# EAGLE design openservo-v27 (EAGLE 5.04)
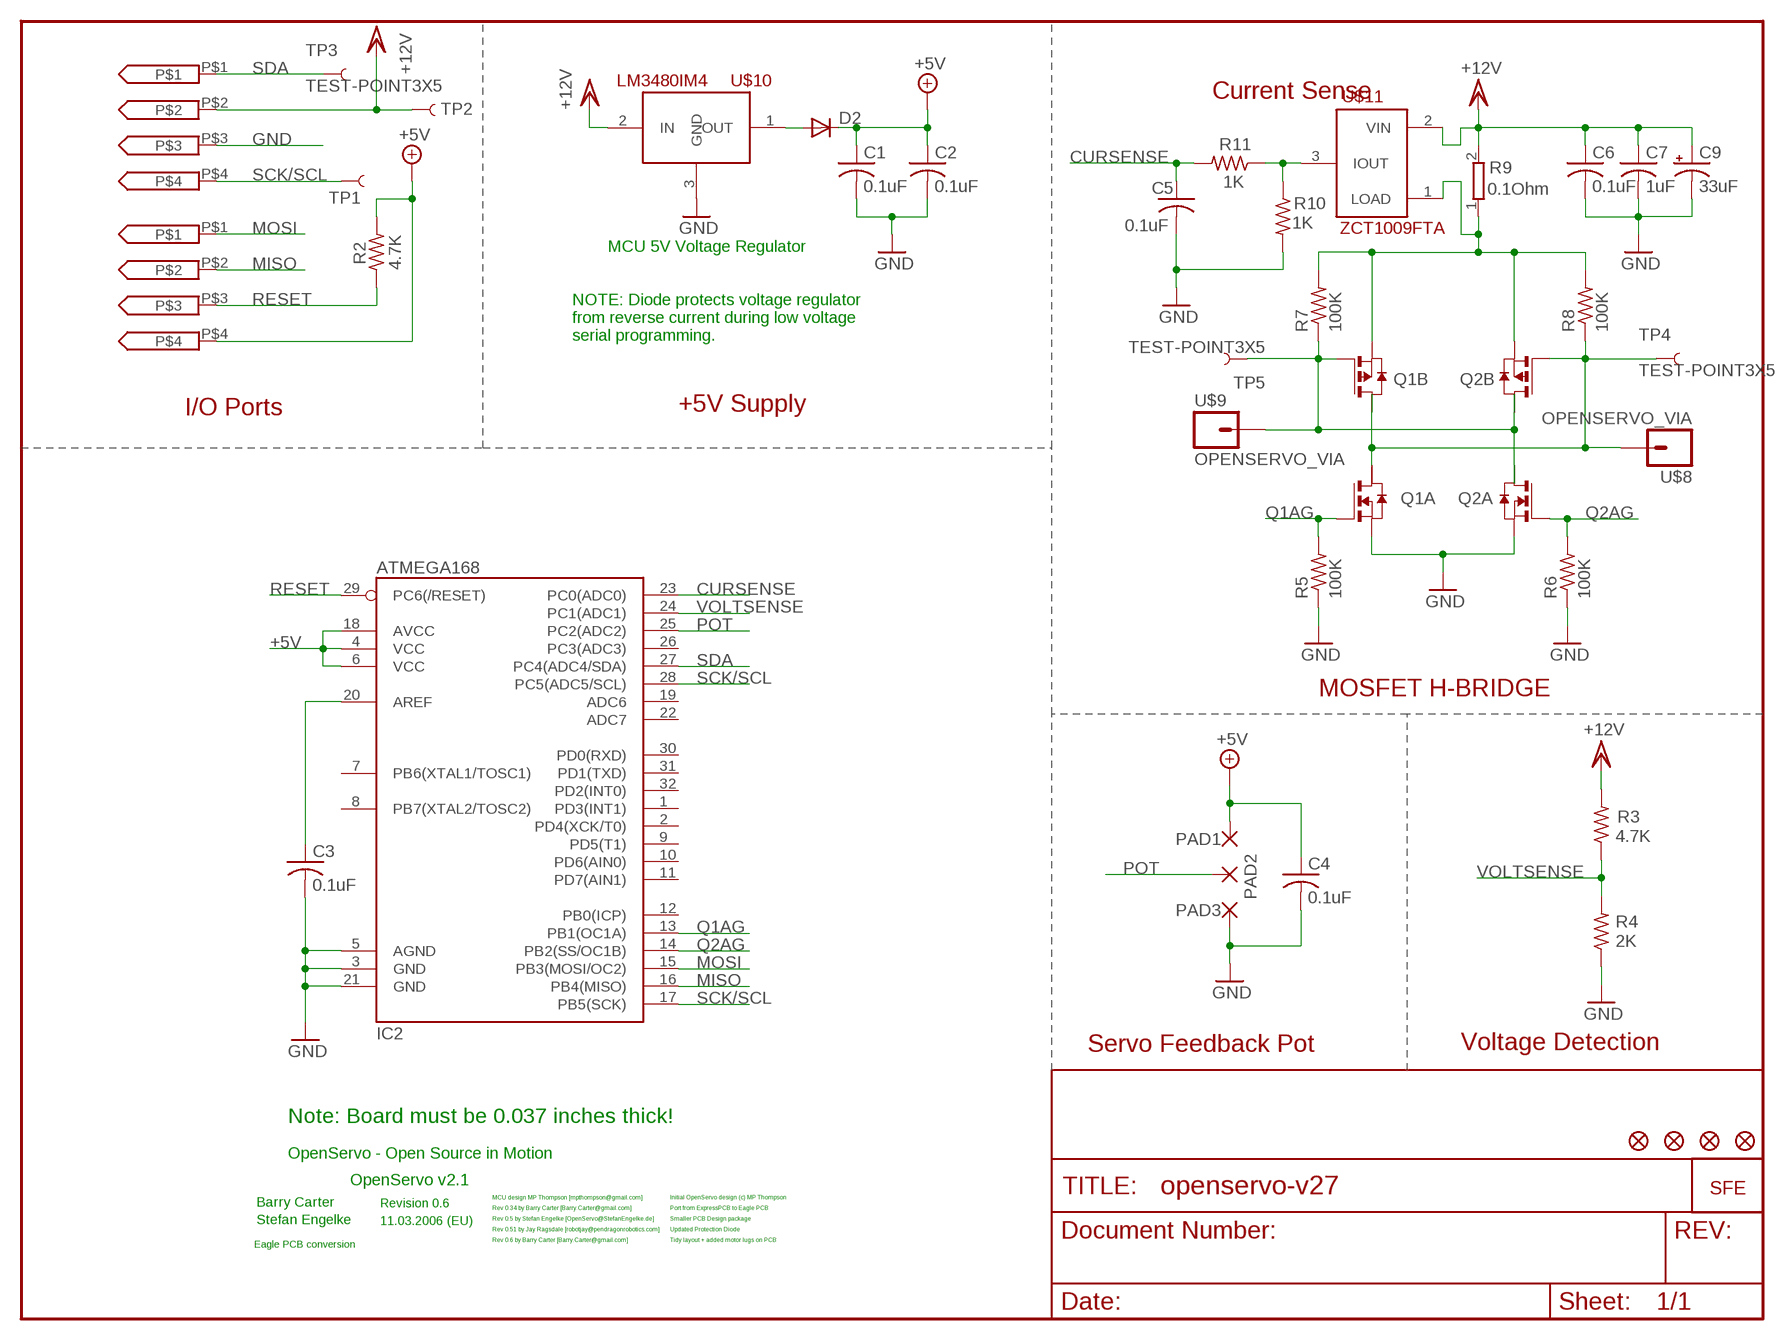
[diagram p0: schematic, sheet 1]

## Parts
C1  0.1uF  C-USC0402  [C0402]
C2  0.1uF  C-USC0402  [C0402]
C3  0.1uF  C-USC0402  [C0402]
C4  0.1uF  C-USC0402  [C0402]
C5  0.1uF  C-USC0402  [C0402]
C6  0.1uF  C-USC0402  [C0402]
C7  1uF  C-USC0402  [C0402]
C9  33uF  CAP_POL3528  [EIA3528]
D2  DIODESOD  [SOD-323]
IC2  ATMEGA168  [TQFP32-08]
PAD1  1,6/0,9  [1,6/0,9]
PAD2  1,6/0,9  [1,6/0,9]
PAD3  1,6/0,9  [1,6/0,9]
Q1  PN_MOSFET-SO8  [SO8]
Q2  PN_MOSFET-SO8  [SO8]
R2  4.7K  R-US_R0402  [R0402]
R3  4.7K  R-US_R0402  [R0402]
R4  2K  R-US_R0402  [R0402]
R5  100K  R-US_R0402  [R0402]
R6  100K  R-US_R0402  [R0402]
R7  100K  R-US_R0402  [R0402]
R8  100K  R-US_R0402  [R0402]
R9  0.1Ohm  R1206W  [R1206W]
R10  1K  R-US_R0402  [R0402]
R11  1K  R-US_R0402  [R0402]
TP1  TEST-POINT3X5  [PAD.03X.05]
TP2  TEST-POINT3X5  [PAD.03X.05]
TP3  TEST-POINT3X5  [PAD.03X.05]
TP4  TEST-POINT3X5  [PAD.03X.05]
TP5  TEST-POINT3X5  [PAD.03X.05]
U$1  4-EDGEVERSION2  4-EDGE  [4-PIN-EDGE]
U$2  4-EDGEVERSION2  4-EDGE  [4-PIN-EDGE]
U$3  FIDUCIAL1X2  [FIDUCIAL-1X2]
U$4  FIDUCIAL1X2  [FIDUCIAL-1X2]
U$5  FIDUCIAL1X2  [FIDUCIAL-1X2]
U$6  FIDUCIAL1X2  [FIDUCIAL-1X2]
U$7  LOGO-SFESK  [SFE-LOGO-FLAME]
U$8  OPENSERVO_VIA  [OPENSERVO_VIA]
U$9  OPENSERVO_VIA  [OPENSERVO_VIA]
U$10  LM3480IM4  [SOT23-3]
U$11  ZCT1009FTA  [SOT23-3]

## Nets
+5V: C1.1 C2.1 C4.1 D2.1(C) IC2.4(VCC) IC2.6(VCC) IC2.18(AVCC) PAD1.1(P) R2.2 U$2.P$4
CURSENSE: C5.1 IC2.23(PC0(ADC0)) R11.2
GND: C1.2 C2.2 C3.2 C4.2 C5.2 C6.2 C7.2 C9.C(-) IC2.3(GND) IC2.5(AGND) IC2.21(GND) PAD3.1(P) Q1.1(A:S) Q2.1(A:S) R4.1 R5.1 R6.1 R10.2 U$1.P$3 U$10.3(GND)
MISO: IC2.16(PB4(MISO)) U$2.P$2
MOSI: IC2.15(PB3(MOSI/OC2)) U$2.P$1
N$1: D2.2(A) U$10.1(OUT)
N$4: Q1.4(B:G) Q2.5(B:D) Q2.6(B:D2) Q2.7(A:D) Q2.8(A:D2) R7.1 TP5.P$1 U$9.P$1
N$5: Q1.5(B:D) Q1.6(B:D2) Q1.7(A:D) Q2.4(B:G) R8.1 TP4.P$1 U$8.P$1
N$10: Q1.3(B:S) Q2.3(B:S) R7.2 R8.2 R9.1 U$11.1(LOAD)
N$12: R10.1 R11.1 U$11.3(IOUT)
N$21: C3.1 IC2.20(AREF)
POT: IC2.25(PC2(ADC2)) PAD2.1(P)
Q1AG: IC2.13(PB1(OC1A)) Q1.2(A:G) R5.2
Q2AG: IC2.14(PB2(SS/OC1B)) Q2.2(A:G) R6.2
RESET: IC2.29(PC6(/RESET)) R2.1 U$2.P$3
SCK/SCL: IC2.17(PB5(SCK)) IC2.28(PC5(ADC5/SCL)) TP1.P$1 U$1.P$4
SDA: IC2.27(PC4(ADC4/SDA)) TP3.P$1 U$1.P$1
VCC/2: C6.1 C7.1 C9.A(+) R3.2 R9.2 TP2.P$1 U$1.P$2 U$10.2(IN) U$11.2(VIN) ; supply symbol labelled +12V
VOLTSENSE: IC2.24(PC1(ADC1)) R3.1 R4.2
Unconnected: IC2.1(PD3(INT1)) IC2.2(PD4(XCK/T0)) IC2.7(PB6(XTAL1/TOSC1)) IC2.8(PB7(XTAL2/TOSC2)) IC2.9(PD5(T1)) IC2.10(PD6(AIN0)) IC2.11(PD7(AIN1)) IC2.12(PB0(ICP)) IC2.19(ADC6) IC2.22(ADC7) IC2.26(PC3(ADC3)) IC2.30(PD0(RXD)) IC2.31(PD1(TXD)) IC2.32(PD2(INT0)) Q1.8(A:D2)

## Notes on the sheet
- Current Sense
- MCU 5V Voltage Regulator
- NOTE: Diode protects voltage regulator
- from reverse current during low voltage
- serial programming.
- I/O Ports | +5V Supply
- MOSFET H-BRIDGE
- Servo Feedback Pot | Voltage Detection
- Note: Board must be 0.037 inches thick!
- OpenServo - Open Source in Motion
- OpenServo v2.1
- MCU design MP Thompson [mpthompson@gmail.com] | Initial OpenServo design (c) MP Thompson
- Barry Carter | Revision 0.6
- Rev 0.34 by Barry Carter [Barry.Carter@gmail.com] | Port from ExpressPCB to Eagle PCB
- Rev 0.5 by Stefan Engelke [OpenServo@StefanEngelke.de] | Smaller PCB Design package
- Stefan Engelke | 11.03.2006 (EU)
- Rev 0.51 by Jay Ragsdale [robotjay@pendragonrobotics.com] | Updated Protection Diode
- Rev 0.6 by Barry Carter [Barry.Carter@gmail.com] | Tidy layout + added motor lugs on PCB
- Eagle PCB conversion

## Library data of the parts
C1-C7 = rcl:C-US: CAPACITOR, American symbol
C9 = SparkFun:CAP_POL: Capacitor Polarized
D2 = SparkFun:DIODE: Diode
IC2 = SparkFun:ATMEGA168
PAD1-PAD3 = wirepad:1,6/0,9: THROUGH-HOLE PAD
Q1 Q2 = zetex:PN_MOSFET-: DUAL N AND P-CHANNEL ENHANCEMENT MODE MOSFET source ZXMD63C02.pdf from http://www.zetex.com/
R2-R8 R10 R11 = rcl:R-US_: RESISTOR, American symbol
R9 = openservo:R1206W
TP1-TP5 = SparkFun:TEST-POINT
U$1 U$2 = openservo:4-EDGE
U$3-U$6 = SparkFun:FIDUCIAL: Fiducial Alignment Points
U$7 = SparkFun:LOGO-SFE: Spark Fun Electronics PCB Logo
U$8 U$9 = SparkFun:OPENSERVO_VIA
U$10 = SparkFun:LM3480IM4
U$11 = SparkFun:ZCT1009FTA

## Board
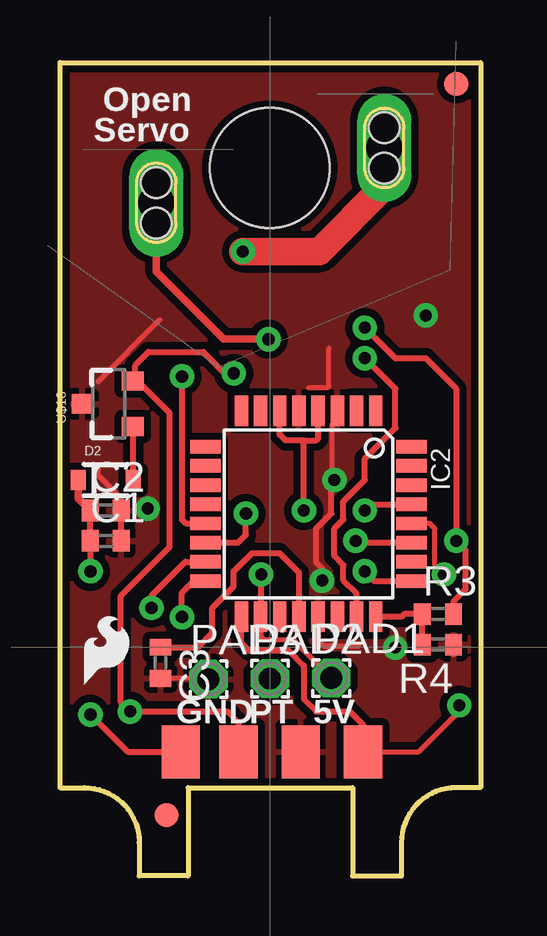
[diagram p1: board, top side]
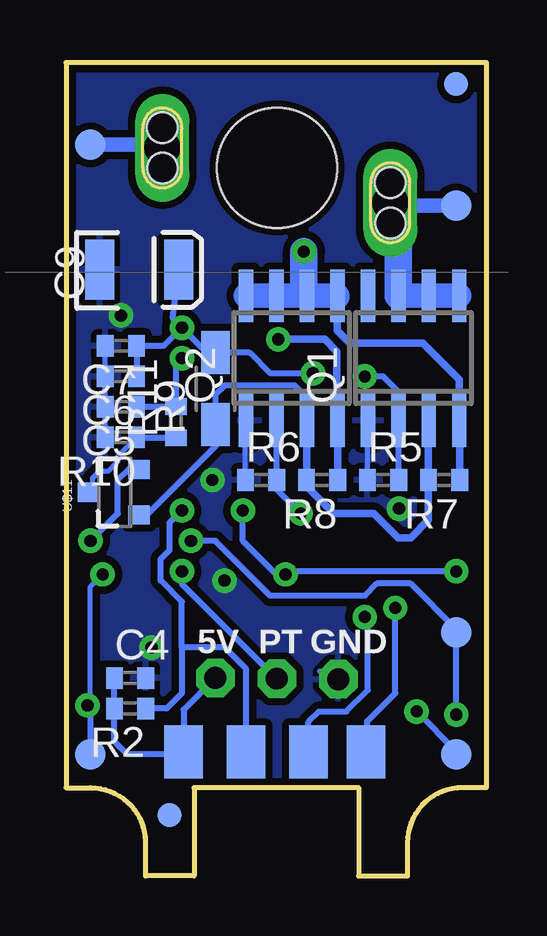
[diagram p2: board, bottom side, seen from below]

Size 17.53 x 33.91 mm. Coordinates in mm from the lower left corner, seen from the top.
Outline: 0,3.68 0,33.91 17.53,33.91 17.53,3.68 16.51,3.68 arc90 14.22,1.4 14.22,0 12.19,0 12.19,3.68 5.33,3.68 5.33,0 3.3,0 3.3,1.4 arc90 1.02,3.68 0,3.68
Copper layers (1*16): Top 0.035mm / dielectric 1.5mm / Bottom 0.035mm
Design rules "SparkFun": minimum track width 8mil, minimum drill 20mil, track to track 8mil, track to pad 8mil, pad to pad 8mil, via to via 8mil, smd to smd 8mil, copper to edge 10mil, drill to drill 8mil, minimum pad ring 12mil, minimum via ring 10mil, stop-mask expansion 4mil, vias tented up to drill 25mil, thermal gap 10mil
Holes 5 mm at 8.74,29.52
tKeepout: area 0.1,0 to 2.1,2; area 15.8,0 to 17.8,2; area 2.5,25.4 to 7.6,29.2; area 10.2,28.3 to 15.2,33
bKeepout: area 2.5,25.4 to 7.6,29.2; area 10.2,29.2 to 15.2,33

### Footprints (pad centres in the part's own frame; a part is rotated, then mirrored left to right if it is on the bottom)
C0402 = smd 0.7 x 0.9: 1 -0.65,0; 2 0.65,0
EIA3528 = smd 1.2 x 2.5: A 1.65,0; C -1.65,0
SOD-323 = smd 0.63 x 0.83: 1 -1.15,0; 2 1.15,0
TQFP32-08 = smd 1.27 x 0.559: 1 -4.293,2.8; 2 -4.293,2; 3 -4.293,1.2; 4 -4.293,0.4; 5 -4.293,-0.4; 6 -4.293,-1.2; 7 -4.293,-2; 8 -4.293,-2.8; 17 4.293,-2.8; 18 4.293,-2; 19 4.293,-1.2; 20 4.293,-0.4; 21 4.293,0.4; 22 4.293,1.2; 23 4.293,2; 24 4.293,2.8 | smd 0.559 x 1.27: 9 -2.8,-4.293; 10 -2,-4.293; 11 -1.2,-4.293; 12 -0.4,-4.293; 13 0.4,-4.293; 14 1.2,-4.293; 15 2,-4.293; 16 2.8,-4.293; 25 2.8,4.293; 26 2,4.293; 27 1.2,4.293; 28 0.4,4.293; 29 -0.4,4.293; 30 -1.2,4.293; 31 -2,4.293; 32 -2.8,4.293
1,6/0,9 = drill 0.914 pad 1.6 octagon: 1 0,0
SO8 = smd 0.6 x 2.2: 1 -1.905,-2.6; 2 -0.635,-2.6; 3 0.635,-2.6; 4 1.905,-2.6; 5 1.905,2.6; 6 0.635,2.6; 7 -0.635,2.6; 8 -1.905,2.6
R0402 = smd 0.7 x 0.9: 1 -0.65,0; 2 0.65,0
R1206W = smd 1.8 x 1.2: 1 -1.499,0; 2 1.499,0
PAD.03X.05 = smd 1.27 x 1.27: P$1 0,0
4-PIN-EDGE = smd 2.2 x 1.6: P$1 1.2,4.2; P$2 1.2,1.8; P$3 1.2,-0.8; P$4 1.2,-3.4
FIDUCIAL-1X2 = smd 1 x 1: 1 0,0
OPENSERVO_VIA = drill 1.5 long: P$1 0,0 | hole 1.27: -0.843,0.005; 0.843,0
SOT23-3 = smd 0.8 x 0.9: 1 -0.95,-1; 2 0.95,-1; 3 0,1.1

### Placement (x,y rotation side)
C1  1.91,13.97 0 top
C2  1.91,15.24 0 top
C3  4.19,8.89 270 top
C4  14.86,8.26 0 bottom
C5  15.24,19.56 180 bottom
C6  15.24,20.83 180 bottom
C7  15.24,22.1 180 bottom
C9  14.48,25.27 0 bottom
D2  1.91,16.51 0 top
IC2  10.35,15.1 270 top
PAD1  11.3,8.26 0 top
PAD2  8.75,8.23 0 top
PAD3  6.18,8.2 0 top
Q1  3.05,21.59 0 bottom
Q2  8.13,21.59 0 bottom
R2  14.86,6.99 180 bottom
R3  15.75,10.92 0 top
R4  15.75,9.65 180 top
R5  4.32,16.51 0 bottom
R6  9.4,16.51 0 bottom
R7  1.78,16.51 180 bottom
R8  6.86,16.51 180 bottom
R9  11.3,20.32 90 bottom
R10  15.24,18.29 180 bottom
R11  12.95,18.92 90 bottom
TP1  16.51,5.08 0 bottom
TP2  1.27,5.08 0 bottom
TP3  1.27,10.16 0 bottom
TP4  1.27,27.94 0 bottom
TP5  16.51,30.48 0 bottom
U$1  9.23,3.98 90 top
U$2  9.23,6.38 270 bottom
U$3  4.45,2.54 0 top
U$4  16.51,33.02 0 top
U$5  1.27,33.02 0 bottom
U$6  13.21,2.54 0 bottom
U$7  1.02,8 0 top
U$8  4.01,28.07 90 top
U$9  13.51,30.35 90 top
U$10  2.03,19.68 90 top
U$11  15.49,16 90 bottom
U$12  [CREATIVE_COMMONS]  not placed on the board

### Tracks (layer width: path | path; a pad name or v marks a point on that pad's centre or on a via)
+5V  (via drill 0.51)
  Top 0.203: IC2.18 8.36,9.98 8.48,9.86 9.7,9.86 PAD1.1
  Top 0.254: C2.1 1.25,14.11 1.27,14.1 1.25,14.08 C1.1 1.25,12.71 v1.27,12.7 | IC2.18 8.36,12.55 v8.38,12.57 | IC2.6 9.15,18.4 9.4,18.16 10.16,18.16 | v10.16,15.24 10.16,18.16 | IC2.4 10.76,18.25 10.67,18.16 10.16,18.16
  Top 0.305: D2.1 0.76,15.74 C2.1
  Bottom 0.254: C4.1 15.62,8.26 15.51,8.14 R2.2 15.51,5.6 14.99,5.08 12.7,5.08 12.6,5.18 | 12.6,5.18 12.57,5.21 | 12.6,5.18 U$2.P$4 12.63,6.93 PAD1.1 | v1.27,12.7 8.26,12.7 v8.38,12.57 8.76,12.57 10.16,13.97 v10.16,15.24
CURSENSE  (via drill 0.51)
  Top 0.254: v12.7,21.59 13.97,20.32 13.97,18.67 12.7,17.4 12.7,16.51 11.81,15.62 11.81,14.86 11.43,14.48 11.43,13.34 11.81,12.95 11.81,12.32 12.36,11.78 IC2.23
  Bottom 0.254: v12.7,21.59 12.95,21.34 R11.2 12.97,19.56 C5.1
GND  (via drill 0.51)
  Top 0.203: C3.2 4.62,8.26 5.38,8.26 PAD3.1 | 10.36,20.34 11.15,20.34 11.2,20.42 11.2,22 | 11.4,9.6 12.45,9.6 | 11.35,16.51 11.35,18.77 IC2.3 | 1.57,20.6 4.17,23.19
  Top 0.254: 2.54,15.24 C2.2 | C1.2 2.56,15.22 2.54,15.24 | R4.1 16.4,9.26 | 1.57,16.97 1.57,16.71 2.54,15.75 2.54,15.24 | v10.92,12.32 10.92,12.83 10.67,13.08 10.67,14.48 11.3,15.11 11.3,16.38 v11.43,16.51 | 11.4,9.6 10.97,9.6 10.76,9.82 IC2.21
  Top 0.305: 2.54,15.24 2.54,15.26
  Bottom 0.203: R10.2 15.9,18.72 15.9,19.13 C5.2 15.9,19.99 15.9,20.4 C6.2 15.9,21.26 15.9,21.67 C7.2 | Q1.1 4.95,16.94 R5.1 | R6.1 10.06,16.94 10.06,17.91 Q2.1 | C4.2 14.12,8.43 | PAD3.1 6.96,8.53 | C9.C 16,25.27
  other vias: 3.66,15.32 15.24,23.37 13.97,9.53
  pour Bottom (isolate 0.305): 0,33.91 0,3.68 17.53,3.68 17.53,33.88
  pour Top (isolate 0.305): 0,33.91 0,3.68 17.53,3.68 17.5,33.91
MISO  (via drill 0.51)
  Top 0.254: IC2.16 5.57,12.3 5.08,11.81 v5.08,10.79
  Bottom 0.254: U$2.P$2 7.43,6.42 6.99,6.86 5.84,6.86 4.95,7.75 4.95,10.67 v5.08,10.79
MOSI  (via drill 0.51)
  Top 0.254: IC2.15 5.22,13.1 3.81,11.68 v3.81,11.18
  Bottom 0.254: U$2.P$1 4.98,5.18 4.98,6.45 3.81,7.62 v3.81,11.18
N$1
  Top 0.254: U$10.1 3.11,18.73 3.17,18.67 3.06,18.55 D2.2
N$4  (via drill 0.51)
  Top 1.143: U$9.P$1 13.51,28.75 10.79,26.04 v7.62,26.04
  Bottom 0.254: Q1.4 1.14,19.05 1.13,19.04
  Bottom 0.305: R7.1 1.13,19.04 | 1.14,19.05 1.14,20.7 2.67,22.23 5.71,22.23 6.22,22.73 Q2.5
  Bottom 0.61: U$9.P$1 13.64,30.48 TP5.P$1
  Bottom 1.016: Q2.8 8.96,24.19 8.89,24.26 8.82,24.19 Q2.7 7.81,24.19 | Q2.6 7.49,24.13 7.55,24.19 7.81,24.19 | Q2.5 6.22,24.13 6.28,24.19 Q2.6 | Q2.6 7.81,24.19
  Bottom 1.143: v7.62,26.04 7.62,24.32 Q2.6
N$5  (via drill 0.51)
  Top 0.305: v8.69,22.38 6.83,22.38 4.45,24.77 | 4.45,24.77 4.19,25.02 | U$8.P$1 4.01,25.2 4.45,24.77
  Bottom 0.254: Q2.4 6.22,18.8 6.21,18.78
  Bottom 0.305: R8.1 6.21,18.78 | Q2.4 6.25,20.07 6.25,21.87 6.76,22.38 v8.69,22.38
  Bottom 0.61: U$8.P$1 3.89,27.94 TP4.P$1
  Bottom 1.016: Q1.5 2.35,24.19 2.41,24.13 Q1.6 3.62,24.19 3.68,24.13 Q1.7
  Bottom 1.143: Q1.7 3.68,27.74 U$8.P$1
N$10
  Bottom 0.203: 14.26,14.9 14.22,14.86 | 14.26,14.95 14.26,14.9 | U$11.1 14.42,15.05 14.26,14.9
  Bottom 0.254: R9.1 11.3,18.92 | Q1.3 2.41,18.92 2.43,18.91 | 7.51,18.91 7.49,18.92 Q2.3 7.49,19.94 8,20.45 10.92,20.45 11.3,20.07 R9.1 | R9.1 11.3,17.91 14.26,14.95
  Bottom 0.305: 2.43,18.91 R7.2 2.43,14.84 3.17,14.1 3.68,14.1 4.7,15.11 6.38,15.11 7.51,16.25 R8.2 7.51,18.91
N$12
  Bottom 0.203: R10.1 15.37,17.51 15.37,17.27 15.75,16.89 16.13,16.89 16.42,16.6 16.42,16.09 16.51,16 U$11.3
  Bottom 0.254: 14.59,18.18 R10.1 12.95,18.29 R11.1
N$21
  Top 0.254: C3.1 5.73,9.54 6.35,10.16 6.35,11.18 7.24,12.06 7.24,12.7 8,13.46 9.14,13.46 9.96,12.65 IC2.20
POT  (via drill 0.51)
  Top 0.254: IC2.25 13.1,12.3 v12.7,12.7
  Bottom 0.254: v12.7,12.7 12.7,12.18 PAD2.1
Q1AG  (via drill 0.51)
  Top 0.254: IC2.13 5.24,14.7 5.08,14.86 v5.08,20.83
  Bottom 0.254: R5.2 3.67,18.91 3.68,18.92 Q1.2 3.68,20.19 4.32,20.83 v5.08,20.83
Q2AG  (via drill 0.51)
  Top 0.254: IC2.14 7.42,13.9 7.75,14.22 v7.75,15.11
  Bottom 0.254: Q2.2 8.76,18.92 8.64,18.8 8.75,18.68 R6.2 8.75,16.11 v7.75,15.11
RESET  (via drill 0.51)
  Top 0.254: IC2.29 12.96,15.5 v12.7,15.24
  Bottom 0.254: R2.1 13.34,6.99 12.7,7.62 12.7,9.53 | U$2.P$3 10.03,8.63 10.92,9.53 12.7,9.53 | 12.7,9.53 12.7,11.43 13.59,12.32 13.59,13.21 13.21,13.59 13.21,14.73 v12.7,15.24
SCK/SCL  (via drill 0.51)
  Top 0.203: IC2.28 15.4,14.7 15.62,14.48 15.62,12.95 v16,12.57 | U$1.P$4 14.96,5.18 16.64,6.86 v16.64,7.11
  Top 0.254: U$1.P$4 12.63,6.29 12.06,6.86 10.67,6.86 10.16,7.37 10.16,8.76 9.53,9.4 7.87,9.4 7.55,9.72 IC2.17
  Bottom 0.203: v16,12.57 16.51,12.06 16.51,7.24 v16.64,7.11
  Bottom 0.254: v16.64,7.11 16.51,6.86 | 16.51,7.24 TP1.P$1
SDA  (via drill 0.51)
  Top 0.254: IC2.27 12.39,13.9 v12.32,13.97 | U$1.P$1 2.82,5.18 v1.27,6.73
  Bottom 0.254: v12.32,13.97 11.3,13.97 9.02,11.68 5.08,11.68 4.57,12.19 3.17,12.19 1.27,10.29 TP3.P$1 v1.27,6.73 1.27,6.6
VCC/2  (via drill 0.51)
  Top 0.254: U$1.P$2 7.43,6.41 6.99,6.86 v2.92,6.86 2.54,7.24 2.54,11.68 4.57,13.72 4.57,19.3 3.17,20.7 3.11,20.64 U$10.2 2.98,20.64 | v12.7,22.86 13.97,21.59 15.24,21.59 16.51,20.32 v16.51,13.97 16.89,13.59 16.89,11.94 16.4,11.45 R3.2 | v7.24,20.95 6.86,20.95 5.97,21.84 3.68,21.84 3.14,21.3 3.14,20.79 2.98,20.64 | 2.98,20.64 2.92,20.57
  Bottom 0.203: 14.49,17 14.48,17.02 | 14.49,17 U$11.2 | 14.92,16.95 14.54,16.95 14.49,17
  Bottom 0.254: 14.92,16.95 15.37,16.51 15.37,15.11 v16.51,13.97 | v12.7,22.86 11.66,21.82 R9.2 9.88,21.82 9.02,20.95 v7.24,20.95 | C9.A 13.08,23.24 v12.7,22.86 | C6.1 C7.1 13.46,22.1 v12.7,22.86 | TP2.P$1 1.27,5.21 v2.92,6.86
VOLTSENSE
  Top 0.254: IC2.24 14.23,10.8 14.35,10.92 R3.1 R4.2

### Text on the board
tPlace: Open | Servo | GND | PT | 5V
bPlace: GND | PT | 5V
tNames: SparkFun Electronics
